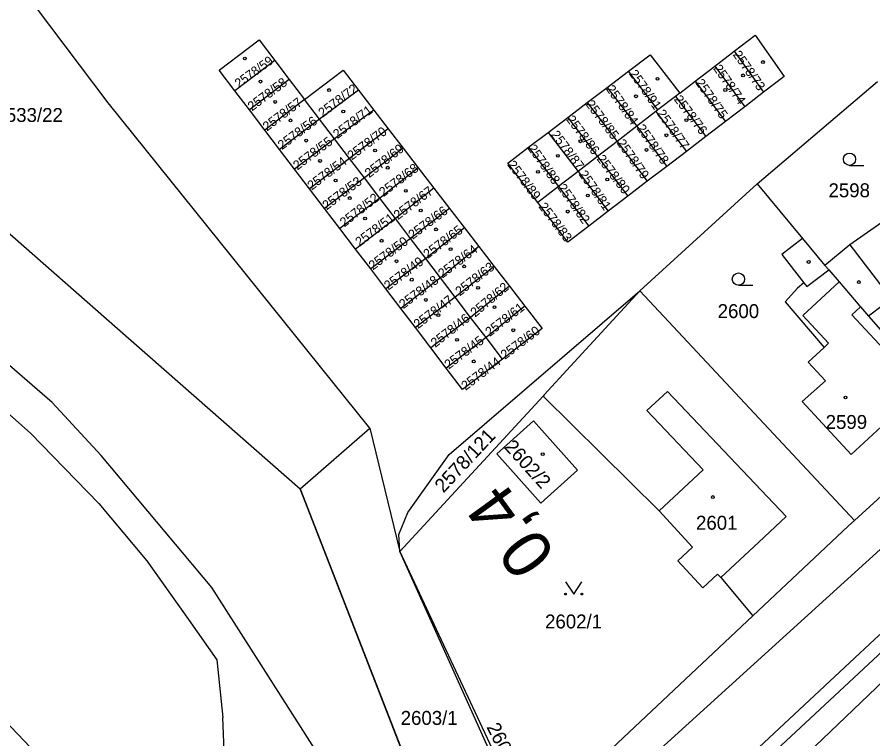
# Model space of a CAD drawing. Extents: x -527335 to -526256, y -1079142 to -1077809.
# Drawn here: x -526804.7 to -526700.3, y -1078442 to -1078353.9 of the extents above; entities that cross this region are included whole.
import ezdxf

# ---------------------------------------------------------------- set-up
doc = ezdxf.new("R2010")
doc.units = 0
for name, color, linetype in [('Vrstva 1', 7, 'Continuous'), ('Vrstva 2', 7, 'Continuous'), ('Vrstva 3', 7, 'Continuous'), ('Vrstva 4', 7, 'Continuous'), ('Vrstva 5', 7, 'Continuous'), ('Vrstva 54', 7, 'Continuous'), ('Vrstva 7', 7, 'Continuous')]:
    doc.layers.add(name, color=color, linetype=linetype)

msp = doc.modelspace()

# ---------------------------------------------------------------- linework, layer by layer
at = {"layer": 'Vrstva 1'}
for p, q in [((-526719.62, -1078359.93), (-526717.25, -1078358.1)), ((-526717.25, -1078358.1), (-526713.66, -1078363.1)), ((-526773.29, -1078359.21), (-526778.15, -1078362.93)), ((-526773.29, -1078359.21), (-526771.51, -1078361.55)), ((-526722, -1078361.76), (-526719.62, -1078359.93)), ((-526719.62, -1078359.93), (-526715.97, -1078364.88)), ((-526732.74, -1078362.52), (-526730.16, -1078360.55)), ((-526726.55, -1078365.27), (-526730.16, -1078360.55)), ((-526771.51, -1078361.55), (-526776.36, -1078365.27)), ((-526771.51, -1078361.55), (-526769.64, -1078363.99)), ((-526723.9, -1078363.23), (-526722, -1078361.76)), ((-526722, -1078361.76), (-526718.33, -1078366.69)), ((-526714.46, -1078374.28), (-526699.79, -1078361.79)), ((-526776.36, -1078365.27), (-526778.15, -1078362.93)), ((-526763.09, -1078362.84), (-526767.83, -1078366.37)), ((-526763.09, -1078362.84), (-526761.21, -1078365.28)), ((-526735.17, -1078364.36), (-526732.74, -1078362.52)), ((-526732.74, -1078362.52), (-526729.13, -1078367.26)), ((-526723.9, -1078363.23), (-526724.41, -1078363.63)), ((-526713.66, -1078363.1), (-526715.97, -1078364.88)), ((-526769.64, -1078363.99), (-526774.49, -1078367.74)), ((-526767.83, -1078366.37), (-526769.64, -1078363.99)), ((-526724.41, -1078363.63), (-526726.55, -1078365.27)), ((-526724.41, -1078363.63), (-526720.71, -1078368.51)), ((-526774.49, -1078367.74), (-526776.36, -1078365.27)), ((-526761.21, -1078365.28), (-526766.01, -1078368.77)), ((-526761.21, -1078365.28), (-526759.44, -1078367.57)), ((-526737.56, -1078366.18), (-526735.17, -1078364.36)), ((-526735.17, -1078364.36), (-526731.54, -1078369.12)), ((-526726.55, -1078365.27), (-526726.79, -1078365.46)), ((-526715.97, -1078364.88), (-526718.33, -1078366.69)), ((-526767.83, -1078366.37), (-526772.69, -1078370.09)), ((-526766.01, -1078368.77), (-526767.83, -1078366.37)), ((-526739.94, -1078368), (-526737.56, -1078366.18)), ((-526737.56, -1078366.18), (-526733.92, -1078370.95)), ((-526726.79, -1078365.46), (-526729.13, -1078367.26)), ((-526726.79, -1078365.46), (-526723.09, -1078370.33)), ((-526729.13, -1078367.26), (-526731.54, -1078369.12)), ((-526729.13, -1078367.26), (-526725.47, -1078372.15)), ((-526718.33, -1078366.69), (-526720.71, -1078368.51)), ((-526772.69, -1078370.09), (-526774.49, -1078367.74)), ((-526759.44, -1078367.57), (-526764.18, -1078371.17)), ((-526759.44, -1078367.57), (-526757.63, -1078369.93)), ((-526742.33, -1078369.81), (-526739.94, -1078368)), ((-526739.94, -1078368), (-526736.3, -1078372.78)), ((-526766.01, -1078368.77), (-526770.86, -1078372.49)), ((-526764.18, -1078371.17), (-526766.01, -1078368.77)), ((-526731.54, -1078369.12), (-526733.92, -1078370.95)), ((-526731.54, -1078369.12), (-526727.85, -1078373.97)), ((-526720.71, -1078368.51), (-526723.09, -1078370.33)), ((-526770.86, -1078372.49), (-526772.69, -1078370.09)), ((-526757.63, -1078369.93), (-526762.36, -1078373.56)), ((-526757.63, -1078369.93), (-526755.79, -1078372.32)), ((-526742.33, -1078369.81), (-526738.67, -1078374.61)), ((-526723.09, -1078370.33), (-526725.47, -1078372.15)), ((-526764.18, -1078371.17), (-526769.03, -1078374.89)), ((-526762.36, -1078373.56), (-526764.18, -1078371.17)), ((-526733.92, -1078370.95), (-526736.3, -1078372.78)), ((-526733.92, -1078370.95), (-526730.23, -1078375.79)), ((-526769.03, -1078374.89), (-526770.86, -1078372.49)), ((-526755.79, -1078372.32), (-526760.48, -1078376.03)), ((-526755.79, -1078372.32), (-526753.87, -1078374.82)), ((-526725.47, -1078372.15), (-526727.85, -1078373.97)), ((-526762.36, -1078373.56), (-526767.21, -1078377.28)), ((-526760.48, -1078376.03), (-526762.36, -1078373.56)), ((-526736.3, -1078372.78), (-526738.67, -1078374.61)), ((-526736.3, -1078372.78), (-526732.61, -1078377.62)), ((-526738.67, -1078374.61), (-526741.21, -1078376.56)), ((-526738.67, -1078374.61), (-526734.98, -1078379.44)), ((-526727.85, -1078373.97), (-526730.23, -1078375.79)), ((-526728.78, -1078387.36), (-526714.46, -1078374.28)), ((-526714.46, -1078374.28), (-526708.91, -1078380.95)), ((-526767.21, -1078377.28), (-526769.03, -1078374.89)), ((-526753.87, -1078374.82), (-526758.57, -1078378.53)), ((-526753.87, -1078374.82), (-526751.97, -1078377.29)), ((-526730.23, -1078375.79), (-526732.61, -1078377.62)), ((-526760.48, -1078376.03), (-526765.34, -1078379.75)), ((-526758.57, -1078378.53), (-526760.48, -1078376.03)), ((-526765.34, -1078379.75), (-526767.21, -1078377.28)), ((-526751.97, -1078377.29), (-526756.73, -1078380.96)), ((-526751.97, -1078377.29), (-526750.15, -1078379.65)), ((-526732.61, -1078377.62), (-526734.98, -1078379.44)), ((-526758.57, -1078378.53), (-526763.43, -1078382.25)), ((-526756.73, -1078380.96), (-526758.57, -1078378.53)), ((-526763.43, -1078382.25), (-526765.34, -1078379.75)), ((-526750.15, -1078379.65), (-526754.88, -1078383.38)), ((-526750.15, -1078379.65), (-526748.39, -1078381.94)), ((-526756.73, -1078380.96), (-526761.58, -1078384.67)), ((-526754.88, -1078383.38), (-526756.73, -1078380.96)), ((-526708.91, -1078380.95), (-526706.18, -1078384.23)), ((-526748.39, -1078381.94), (-526753.06, -1078385.77)), ((-526748.39, -1078381.94), (-526746.53, -1078384.36)), ((-526761.58, -1078384.67), (-526763.43, -1078382.25)), ((-526754.88, -1078383.38), (-526759.73, -1078387.1)), ((-526753.06, -1078385.77), (-526754.88, -1078383.38)), ((-526759.73, -1078387.1), (-526761.58, -1078384.67)), ((-526746.53, -1078384.36), (-526751.27, -1078388.11)), ((-526746.53, -1078384.36), (-526744.66, -1078386.78)), ((-526753.06, -1078385.77), (-526757.91, -1078389.49)), ((-526751.27, -1078388.11), (-526753.06, -1078385.77)), ((-526757.91, -1078389.49), (-526759.73, -1078387.1)), ((-526744.66, -1078386.78), (-526749.4, -1078390.58)), ((-526744.66, -1078386.78), (-526742.78, -1078389.23)), ((-526751.27, -1078388.11), (-526756.13, -1078391.83)), ((-526749.4, -1078390.58), (-526751.27, -1078388.11)), ((-526728.78, -1078387.36), (-526702.59, -1078415.38)), ((-526742.78, -1078389.23), (-526747.52, -1078393.05)), ((-526756.13, -1078391.83), (-526757.91, -1078389.49)), ((-526749.4, -1078390.58), (-526754.25, -1078394.3)), ((-526747.52, -1078393.05), (-526749.4, -1078390.58)), ((-526754.25, -1078394.3), (-526756.13, -1078391.83)), ((-526747.52, -1078393.05), (-526752.37, -1078396.77)), ((-526745.52, -1078395.67), (-526747.52, -1078393.05)), ((-526752.37, -1078396.77), (-526754.25, -1078394.3)), ((-526740.57, -1078400.18), (-526758.04, -1078419.17)), ((-526770.17, -1078411.49), (-526761.68, -1078404.12)), ((-526761.68, -1078404.12), (-526758.04, -1078419.17)), ((-526702.59, -1078415.38), (-526694.13, -1078407.6)), ((-526749.3, -1078465.23), (-526770.17, -1078411.49)), ((-526742.65, -1078453.3), (-526758.04, -1078419.17)), ((-526758.04, -1078419.17), (-526742.34, -1078452.74)), ((-526714.96, -1078427.01), (-526742.34, -1078452.74))]:
    msp.add_line(p, q, dxfattribs=at)
for points in [[(-526538.39, -1078327.72), (-526540.03, -1078327.15), (-526546.04, -1078326.1), (-526550.79, -1078326.44), (-526558.7, -1078329.17), (-526588.71, -1078343.39), (-526596.49, -1078347.76), (-526612.22, -1078358.58), (-526630.45, -1078371.95), (-526674.07, -1078406.52), (-526700.09, -1078429.86), (-526748.62, -1078475.19)], [(-526761.68, -1078404.12), (-526793.59, -1078364.38), (-526804.2, -1078350.27)], [(-526758.4, -1078472.62), (-526766.27, -1078446.58), (-526780.95, -1078423.56), (-526794.44, -1078407.43), (-526800.43, -1078400.96), (-526814.56, -1078388.75), (-526829.06, -1078378.91), (-526860.51, -1078363.6), (-526886.41, -1078357.78), (-526924.51, -1078355.89), (-526949.93, -1078359.99), (-526973.92, -1078367.12), (-526999.06, -1078381.03), (-527019.7, -1078396.51), (-527044.07, -1078424.46), (-527066.65, -1078463.1), (-527068.91, -1078470.58)], [(-526778.15, -1078362.93), (-526780.06, -1078360.42), (-526775.2, -1078356.7), (-526773.29, -1078359.21)], [(-526717.25, -1078358.1), (-526714.71, -1078356.15), (-526711.16, -1078361.18), (-526713.66, -1078363.1)], [(-526730.16, -1078360.55), (-526727.5, -1078358.52), (-526723.9, -1078363.23)], [(-526769.64, -1078363.99), (-526764.95, -1078360.42), (-526763.09, -1078362.84)], [(-526741.21, -1078376.56), (-526744.87, -1078371.74), (-526742.33, -1078369.81)], [(-526691.04, -1078373.25), (-526703.15, -1078381.73), (-526706.18, -1078384.23)], [(-526811.67, -1078375.09), (-526792.46, -1078391.93), (-526770.17, -1078411.49)], [(-526734.98, -1078379.44), (-526737.53, -1078381.41), (-526741.21, -1078376.56)], [(-526743.04, -1078478.19), (-526726.54, -1078460.31), (-526716.69, -1078451.83), (-526696.21, -1078432.2), (-526671.8, -1078409.48), (-526665.85, -1078404.63), (-526634.47, -1078380.43)], [(-526708.91, -1078380.95), (-526711.44, -1078382.92), (-526708.75, -1078386.36), (-526709.53, -1078387), (-526711.03, -1078388.68), (-526706.28, -1078394.24), (-526708.22, -1078396.05), (-526706.1, -1078398.32), (-526708.98, -1078400.87), (-526703, -1078407.31), (-526699.3, -1078403.92), (-526694.13, -1078407.6)], [(-526706.18, -1078384.23), (-526705.72, -1078384.77), (-526704.44, -1078386.26), (-526701.91, -1078389.21), (-526701.84, -1078389.29), (-526700.86, -1078390.43), (-526699.71, -1078391.78), (-526692.49, -1078400.19), (-526689.66, -1078403.49)], [(-526758.04, -1078419.17), (-526758.14, -1078417.1), (-526757.05, -1078414.38), (-526752.01, -1078407.3), (-526728.78, -1078387.36)], [(-526728.78, -1078387.36), (-526737.23, -1078396.55), (-526740.42, -1078400.02), (-526740.57, -1078400.18)], [(-526742.78, -1078389.23), (-526740.68, -1078391.96), (-526745.52, -1078395.67)], [(-526745.52, -1078395.67), (-526750.37, -1078399.39), (-526752.37, -1078396.77)], [(-526740.57, -1078400.18), (-526726.42, -1078414.21), (-526722.33, -1078418.62), (-526724.12, -1078420.28), (-526721.07, -1078423.59), (-526719.28, -1078421.92), (-526718.89, -1078422.34), (-526714.96, -1078427.01)], [(-526741.75, -1078403.21), (-526736.35, -1078409.25), (-526740.84, -1078413.24), (-526746.21, -1078407.22), (-526741.75, -1078403.21)], [(-526714.96, -1078427.01), (-526703.34, -1078416.08), (-526702.59, -1078415.38)], [(-526838.85, -1078458.45), (-526834.26, -1078463.18), (-526807.84, -1078438.11), (-526795.26, -1078451.29), (-526823.96, -1078478.68), (-526825.34, -1078477.23)]]:
    msp.add_lwpolyline(points, dxfattribs=at)
at = {"layer": 'Vrstva 3'}
for p, q in [((-526703.19, -1078372.04), (-526701.44, -1078372.04)), ((-526716.74, -1078386.66), (-526714.99, -1078386.66))]:
    msp.add_line(p, q, dxfattribs=at)
msp.add_lwpolyline([(-526737.83, -1078422.86), (-526736.83, -1078424.36), (-526735.83, -1078422.86)], dxfattribs=at)
for centre, radius in [((-526703.19, -1078371.29), 0.75), ((-526716.74, -1078385.91), 0.75), ((-526737.83, -1078424.36), 0.1), ((-526735.83, -1078424.36), 0.1)]:
    msp.add_circle(centre, radius, dxfattribs=at)
at = {"layer": 'Vrstva 4'}
for p, q in [((-526703.15, -1078381.73), (-526698.08, -1078388.36)), ((-526708.39, -1078386.82), (-526705.72, -1078384.77)), ((-526708.88, -1078390.35), (-526704.44, -1078386.26)), ((-526708.75, -1078386.36), (-526708.39, -1078386.82)), ((-526701.84, -1078389.29), (-526702.92, -1078390.29)), ((-526699.03, -1078389.07), (-526700.86, -1078390.43)), ((-526705.74, -1078393.74), (-526708.88, -1078390.35)), ((-526702.92, -1078390.29), (-526694.4, -1078399.43)), ((-526816.66, -1078392.88), (-526803.07, -1078404.72)), ((-526706.28, -1078394.24), (-526705.74, -1078393.74)), ((-526727.91, -1078401.95), (-526725.37, -1078399.61)), ((-526725.37, -1078399.61), (-526710.93, -1078414.89)), ((-526721.03, -1078409.18), (-526727.91, -1078401.95)), ((-526803.07, -1078404.72), (-526794.74, -1078413.32)), ((-526726.42, -1078414.21), (-526721.03, -1078409.18)), ((-526794.74, -1078413.32), (-526788.9, -1078420.29)), ((-526710.93, -1078414.89), (-526714.25, -1078418.03)), ((-526739.69, -1078455.4), (-526698.99, -1078418.52)), ((-526714.25, -1078418.03), (-526718.89, -1078422.34)), ((-526788.9, -1078420.29), (-526783.79, -1078427.44)), ((-526783.79, -1078427.44), (-526780.36, -1078432.37)), ((-526699.14, -1078431.3), (-526719.66, -1078450.36)), ((-526780.36, -1078432.37), (-526779.62, -1078439.41)), ((-526778.46, -1078469.48), (-526779.62, -1078439.41))]:
    msp.add_line(p, q, dxfattribs=at)
at = {"layer": 'Vrstva 5'}
for centre in [(-526776.93, -1078358.99), (-526713.75, -1078359.42), (-526716.17, -1078361.05), (-526775.02, -1078361.81), (-526726.61, -1078361.46), (-526766.66, -1078362.84), (-526718.34, -1078362.83), (-526773.23, -1078364.29), (-526729.23, -1078363.59), (-526764.93, -1078365.45), (-526771.37, -1078366.54), (-526723.08, -1078366.51), (-526725.52, -1078368.36), (-526769.46, -1078369.01), (-526736.01, -1078369.09), (-526761.05, -1078370.22), (-526727.95, -1078370.15), (-526767.76, -1078371.49), (-526738.77, -1078370.86), (-526759.51, -1078372.32), (-526741.19, -1078372.81), (-526765.87, -1078373.87), (-526732.73, -1078373.76), (-526757.3, -1078375.14), (-526735.1, -1078375.7), (-526764.14, -1078376.02), (-526755.48, -1078377.53), (-526737.56, -1078377.67), (-526762.27, -1078378.51), (-526753.62, -1078379.84), (-526760.26, -1078381.23), (-526751.84, -1078382.26), (-526758.44, -1078383.73), (-526708.17, -1078383.82), (-526750.19, -1078384.36), (-526756.58, -1078385.98), (-526702.05, -1078386.27), (-526748.49, -1078386.98), (-526754.86, -1078388.45), (-526746.48, -1078389.33), (-526753.33, -1078390.31), (-526744.2, -1078392.16), (-526751.05, -1078393.33), (-526749.02, -1078395.95), (-526703.67, -1078400.36), (-526740.6, -1078407.28), (-526719.86, -1078412.51)]:
    msp.add_circle(centre, 0.175, dxfattribs=at)
at = {"layer": 'Vrstva 54'}
for points in [[(-527073.97, -1078460.17), (-527053.17, -1078420.48), (-527032.18, -1078397.77), (-527014.31, -1078382.24), (-527013.19, -1078381.27), (-527008.42, -1078377.49), (-527001.38, -1078371.92), (-526974.73, -1078357.59), (-526955.89, -1078351.06), (-526922.67, -1078344.37), (-526902.66, -1078344.75), (-526884.52, -1078346.04), (-526843.79, -1078358.29), (-526811.67, -1078375.09), (-526792.46, -1078391.93), (-526770.17, -1078411.49), (-526749.3, -1078465.23)], [(-526766.27, -1078446.58), (-526780.95, -1078423.56), (-526794.44, -1078407.43), (-526800.43, -1078400.96), (-526814.56, -1078388.75), (-526829.06, -1078378.91), (-526829.06, -1078378.91), (-526860.51, -1078363.6), (-526886.41, -1078357.78), (-526924.51, -1078355.89), (-526949.93, -1078359.99), (-526973.92, -1078367.12), (-526999.06, -1078381.03), (-527019.7, -1078396.51), (-527044.07, -1078424.46), (-527066.65, -1078463.1)]]:
    msp.add_lwpolyline(points, dxfattribs=at)

# ---------------------------------------------------------------- texts
at = {"layer": 'Vrstva 2'}
for s, height, rotation, p in [('2578/73', 1.14, 305, (-526717.47, -1078358.51)), ('2578/59', 1.1, 36, (-526777.67, -1078362.61)), ('2578/74', 1.14, 305, (-526719.85, -1078360.21)), ('2578/91', 1.14, 305, (-526730.13, -1078360.84)), ('2578/58', 1.14, 37, (-526776.06, -1078365.45)), ('2578/72', 1.139, 37, (-526767.44, -1078366.22)), ('2578/84', 1.14, 305, (-526732.94, -1078362.7)), ('2578/75', 1.14, 305, (-526722.04, -1078361.95)), ('2578/57', 1.14, 37, (-526774.22, -1078367.9)), ('2578/85', 1.14, 307, (-526735.43, -1078364.58)), ('2578/76', 1.14, 307, (-526724.66, -1078363.98)), ('2578/71', 1.14, 37, (-526765.65, -1078368.84)), ('2578/77', 1.14, 305, (-526726.74, -1078365.7)), ('2578/56', 1.14, 37, (-526772.39, -1078370.17)), ('2578/86', 1.14, 307, (-526737.79, -1078366.44)), ('2578/70', 1.14, 37, (-526763.9, -1078371.45)), ('2578/78', 1.14, 305, (-526729.21, -1078367.5)), ('2578/87', 1.139, 307, (-526739.68, -1078368.3)), ('2578/55', 1.14, 37, (-526770.52, -1078372.66)), ('2578/69', 1.139, 38, (-526761.76, -1078373.6)), ('2578/88', 1.14, 305, (-526742.49, -1078369.95)), ('2578/79', 1.14, 305, (-526731.63, -1078369.31)), ('2578/54', 1.14, 37, (-526768.78, -1078375.11)), ('2578/89', 1.14, 307, (-526744.98, -1078371.96)), ('2578/80', 1.14, 307, (-526734.09, -1078371.24)), ('2578/68', 1.139, 37, (-526760.03, -1078375.92)), ('2578/81', 1.14, 305, (-526736.26, -1078373.12)), ('2578/53', 1.14, 37, (-526766.95, -1078377.53)), ('2578/67', 1.14, 37, (-526758.26, -1078378.72)), ('2578/82', 1.14, 305, (-526738.85, -1078374.76)), ('2578/52', 1.139, 38, (-526764.8, -1078379.61)), ('2578/83', 1.139, 307, (-526741.16, -1078377.08)), ('2578/66', 1.14, 37, (-526756.47, -1078381.12)), ('2578/51', 1.139, 37, (-526762.94, -1078381.99)), ('2578/65', 1.14, 37, (-526754.64, -1078383.47)), ('2578/50', 1.14, 37, (-526761.3, -1078384.86)), ('2578/64', 1.14, 37, (-526752.83, -1078385.85)), ('2578/49', 1.14, 37, (-526759.43, -1078387.32)), ('2578/63', 1.139, 38, (-526750.72, -1078388.03)), ('2578/48', 1.14, 37, (-526757.59, -1078389.59)), ('2578/62', 1.139, 40, (-526748.84, -1078390.61)), ('2578/47', 1.14, 37, (-526755.82, -1078392.02)), ('2578/61', 1.139, 38, (-526747.07, -1078392.98)), ('2578/46', 1.139, 38, (-526753.71, -1078394.31)), ('2578/60', 1.14, 37, (-526745.21, -1078395.77)), ('2578/45', 1.14, 37, (-526752.07, -1078396.96)), ('2578/44', 1.14, 37, (-526750.01, -1078399.55)), ('2578/121', 1.7, 47, (-526752.71, -1078412.09)), ('2602/2', 1.7, 312, (-526745.39, -1078406.46)), ('2603/2', 1.7, 296.5516, (-526747.5, -1078440.57))]:
    msp.add_text(s, height=height, rotation=rotation, dxfattribs=at).set_placement(p)
for s, p in [('2533/22', (-526807.35, -1078366.73)), ('2598', (-526705.75, -1078375.92)), ('2600', (-526719.27, -1078390.67)), ('2599', (-526706.1, -1078404.2)), ('2601', (-526721.91, -1078416.5)), ('2602/1', (-526740.32, -1078428.55)), ('2603/1', (-526757.93, -1078440.32))]:
    msp.add_text(s, height=1.7, dxfattribs=at).set_placement(p)
at = {"layer": 'Vrstva 7'}
msp.add_text('0,4', height=6, rotation=126.0102, dxfattribs=at).set_placement((-526738.83, -1078419.51))

doc.saveas('drawing.dxf')
